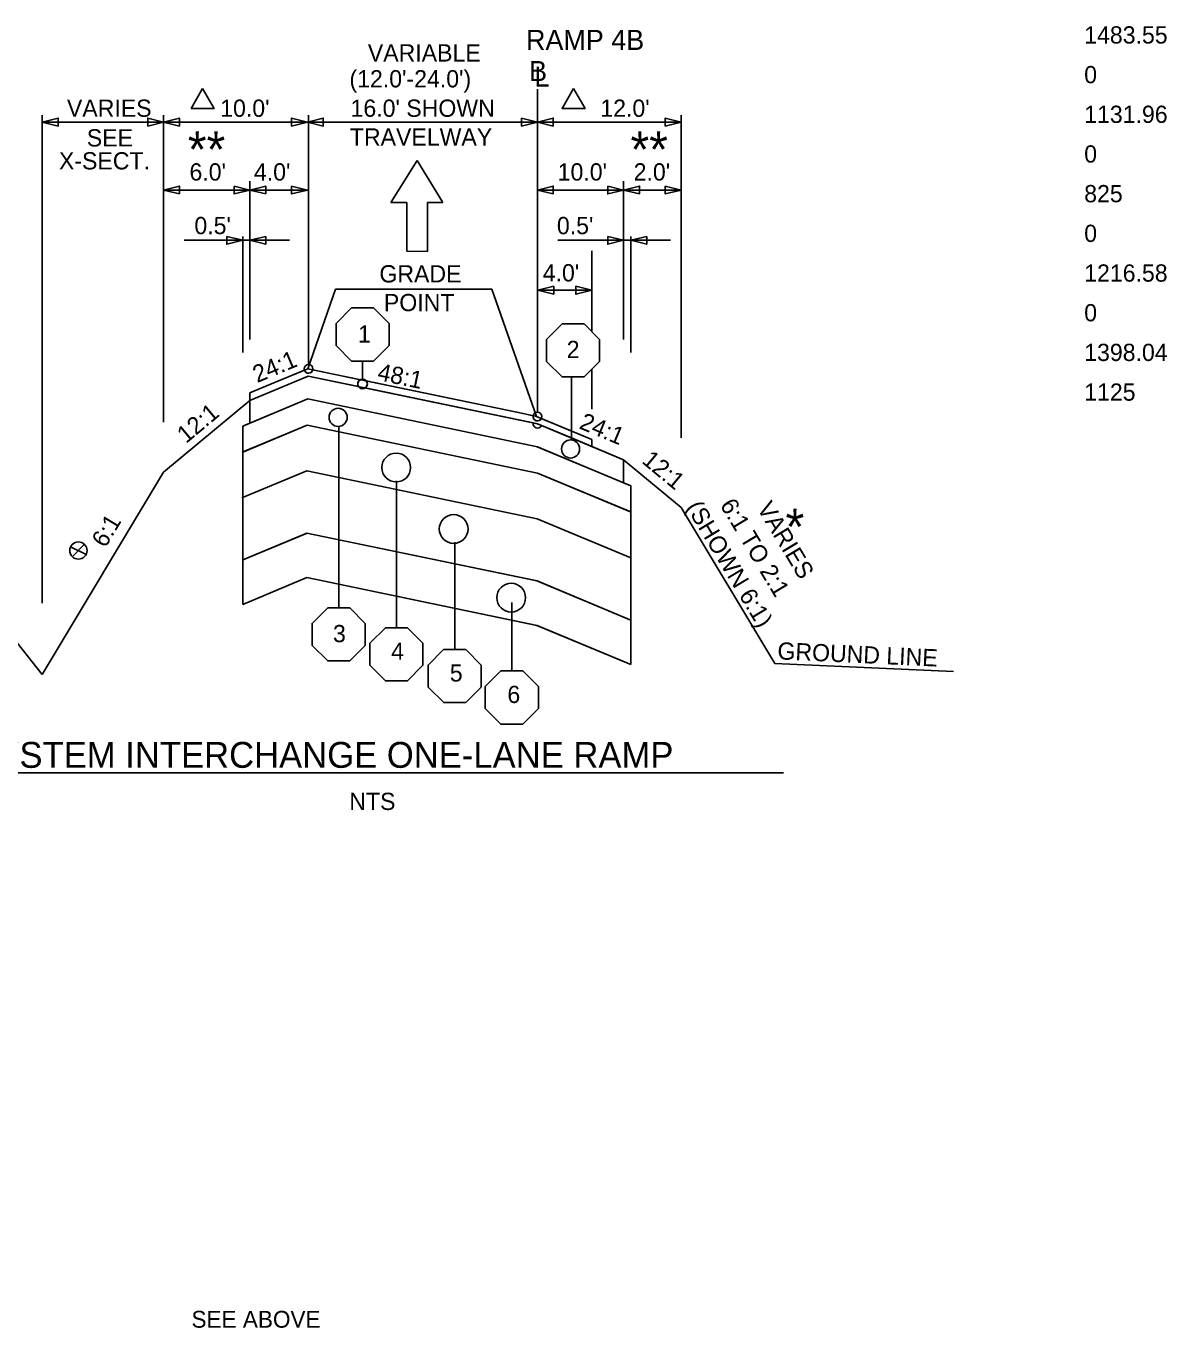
# Model space of a CAD drawing. Extents: x 4932 to 5887, y 4809 to 5473.
# Drawn here: x 5284.3 to 5363.6, y 5044.2 to 5134.7 of the extents above; entities that cross this region are included whole.
import ezdxf

# ---------------------------------------------------------------- set-up
doc = ezdxf.new("R2010")
doc.units = 0
for name, color, linetype in [('Level 2', 7, 'Continuous'), ('Level 20', 7, 'Continuous'), ('Level 25', 7, 'Continuous'), ('RD_QTY_Intermediate', 7, 'Continuous'), ('RD_QTY_Surf_Course', 7, 'Continuous'), ('RD_SHT_Typical', 7, 'Continuous'), ('RD_TX_TypSect', 7, 'Continuous'), ('RD_XS_ExGround', 7, 'Continuous'), ('typical2', 7, 'Continuous'), ('typical_on', 7, 'Continuous')]:
    doc.layers.add(name, color=color, linetype=linetype)

msp = doc.modelspace()

# ---------------------------------------------------------------- linework, layer by layer
at = {"layer": 'Level 2'}
for p, q in [((5299.854, 5107.109), (5299.854, 5107.109)), ((5299.854, 5107.054), (5299.854, 5107.054))]:
    msp.add_line(p, q, dxfattribs=at)
at = {"layer": 'Level 20'}
for p, q in [((5309.668, 5122.448), (5311.49, 5125.362)), ((5311.49, 5125.362), (5313.274, 5122.438)), ((5310.76, 5122.447), (5309.668, 5122.448)), ((5310.76, 5122.447), (5310.76, 5119.047)), ((5312.217, 5122.438), (5313.274, 5122.438)), ((5312.217, 5122.438), (5312.217, 5119.038)), ((5310.76, 5119.047), (5312.217, 5119.038))]:
    msp.add_line(p, q, dxfattribs=at)
at = {"layer": 'Level 25'}
for p, q in [((5303.875, 5110.876), (5305.818, 5116.411)), ((5305.818, 5116.411), (5316.674, 5116.411)), ((5316.674, 5116.411), (5319.78, 5107.562))]:
    msp.add_line(p, q, dxfattribs=at)
at = {"layer": 'RD_QTY_Intermediate'}
for p, q in [((5319.847, 5105.45), (5303.875, 5108.777)), ((5299.355, 5105.084), (5303.847, 5106.956)), ((5299.355, 5106.893), (5299.355, 5105.084)), ((5303.847, 5106.956), (5319.846, 5103.623)), ((5325.845, 5102.931), (5319.847, 5105.45)), ((5319.846, 5103.623), (5326.345, 5100.915)), ((5326.345, 5102.723), (5325.845, 5102.933)), ((5326.345, 5100.915), (5326.345, 5102.723))]:
    msp.add_line(p, q, dxfattribs=at)
for points in [[(5303.875, 5108.777), (5299.854, 5107.102), (5299.355, 5106.893)], [(5325.845, 5102.933), (5325.845, 5102.931)]]:
    msp.add_lwpolyline(points, dxfattribs=at)
at = {"layer": 'RD_QTY_Surf_Course'}
for p, q in [((5303.911, 5110.365), (5299.854, 5108.675)), ((5319.554, 5107.106), (5303.911, 5110.365)), ((5299.854, 5107.102), (5303.875, 5108.777)), ((5299.854, 5108.675), (5299.854, 5107.102)), ((5303.875, 5108.777), (5319.847, 5105.45)), ((5319.847, 5105.45), (5325.845, 5102.933)), ((5325.845, 5102.933), (5325.845, 5104.546))]:
    msp.add_line(p, q, dxfattribs=at)
msp.add_lwpolyline([(5325.845, 5104.546), (5322.209, 5106.061), (5320.124, 5106.93)], dxfattribs=at)
msp.add_circle((5322.152, 5105.298), 0.63, dxfattribs=at)
msp.add_arc((5319.847, 5107.045), 0.3, 168.23191, 337.38014, dxfattribs=at)
at = {"layer": 'RD_SHT_Typical'}
for p, q in [((5301.796, 5110.01), (5303.875, 5110.876)), ((5303.652, 5110.783), (5301.796, 5110.01)), ((5307.538, 5110.113), (5304.234, 5110.801)), ((5299.854, 5108.675), (5303.911, 5110.365)), ((5299.854, 5108.675), (5303.911, 5110.365)), ((5299.854, 5109.201), (5301.796, 5110.01)), ((5301.796, 5110.01), (5299.854, 5109.201)), ((5303.911, 5110.365), (5307.417, 5109.634)), ((5299.854, 5109.201), (5299.854, 5107.102)), ((5299.854, 5109.201), (5299.854, 5108.675)), ((5307.871, 5109.54), (5319.554, 5107.106)), ((5299.854, 5108.675), (5293.857, 5103.677)), ((5299.355, 5106.893), (5303.875, 5108.777)), ((5319.554, 5107.106), (5319.847, 5107.045)), ((5323.624, 5105.961), (5319.78, 5107.562)), ((5325.845, 5104.546), (5319.847, 5107.045)), ((5319.847, 5107.045), (5320.124, 5106.93)), ((5323.624, 5105.961), (5320.117, 5107.422)), ((5299.327, 5105.072), (5303.847, 5106.956)), ((5299.355, 5106.893), (5299.355, 5094.489)), ((5326.345, 5102.723), (5319.823, 5105.44)), ((5323.624, 5105.961), (5323.624, 5105.471)), ((5323.624, 5105.471), (5323.624, 5105.961)), ((5325.845, 5104.546), (5325.845, 5102.931)), ((5325.845, 5104.546), (5329.843, 5101.214)), ((5293.857, 5103.677), (5285.421, 5089.617)), ((5299.304, 5101.896), (5303.825, 5103.78)), ((5326.367, 5100.906), (5319.846, 5103.623)), ((5326.345, 5102.723), (5326.345, 5090.302)), ((5329.843, 5101.214), (5336.346, 5090.376)), ((5326.345, 5097.73), (5319.823, 5100.447)), ((5299.311, 5097.565), (5303.831, 5099.449)), ((5278.835, 5097.851), (5285.421, 5089.617)), ((5299.355, 5094.489), (5303.825, 5096.352)), ((5326.345, 5093.4), (5319.805, 5096.125)), ((5326.345, 5090.302), (5319.805, 5093.026))]:
    msp.add_line(p, q, dxfattribs=at)
for points in [[(5303.875, 5110.876), (5318.85, 5107.756), (5319.78, 5107.562)], [(5303.911, 5110.365), (5319.847, 5107.045)], [(5319.552, 5107.61), (5318.85, 5107.756), (5307.951, 5110.027)], [(5303.875, 5108.777), (5319.847, 5105.45)], [(5303.847, 5106.956), (5319.846, 5103.623)], [(5320.124, 5106.93), (5322.209, 5106.061), (5323.624, 5105.471)], [(5303.825, 5103.78), (5319.823, 5100.447)], [(5303.825, 5099.45), (5319.823, 5096.117)], [(5303.825, 5096.352), (5319.823, 5093.019)]]:
    msp.add_lwpolyline(points, dxfattribs=at)
for centre, radius, start, end in [((5303.941, 5110.862), 0.3, 195.36042, 348.23191), ((5307.693, 5109.819), 0.332, 117.69811, 213.83802), ((5307.693, 5109.819), 0.332, 302.6258, 38.76571), ((5319.846, 5107.549), 0.3, 168.23191, 334.96624)]:
    msp.add_arc(centre, radius, start, end, dxfattribs=at)
at = {"layer": 'RD_TX_TypSect'}
for p, q in [((5319.846, 5130.313), (5319.846, 5107.849)), ((5285.421, 5094.569), (5285.421, 5128.519)), ((5285.421, 5128.034), (5293.857, 5128.034)), ((5293.857, 5107.151), (5293.857, 5128.519)), ((5293.857, 5128.034), (5303.853, 5128.034)), ((5303.853, 5128.034), (5319.847, 5128.034)), ((5303.941, 5128.519), (5303.941, 5111.162)), ((5319.847, 5128.034), (5329.843, 5128.034)), ((5329.843, 5106.068), (5329.843, 5128.519)), ((5293.857, 5123.305), (5299.854, 5123.305)), ((5299.854, 5112.915), (5299.854, 5123.923)), ((5299.854, 5123.305), (5303.853, 5123.305)), ((5319.847, 5123.305), (5325.845, 5123.305)), ((5325.845, 5112.915), (5325.845, 5123.923)), ((5325.845, 5123.305), (5329.843, 5123.305)), ((5295.277, 5119.809), (5299.355, 5119.809)), ((5299.355, 5112.014), (5299.355, 5120.084)), ((5302.62, 5119.809), (5299.355, 5119.809)), ((5321.257, 5119.809), (5325.845, 5119.809)), ((5329.11, 5119.809), (5325.845, 5119.809)), ((5326.345, 5112.014), (5326.345, 5120.084)), ((5323.624, 5113.466), (5323.624, 5119.088)), ((5319.877, 5116.333), (5323.624, 5116.333)), ((5307.693, 5111.408), (5307.693, 5110.151)), ((5323.624, 5108.075), (5323.624, 5110.833)), ((5322.209, 5105.914), (5322.209, 5110.303)), ((5306.03, 5094.246), (5306.03, 5106.889)), ((5310.046, 5092.862), (5310.046, 5103.071)), ((5303.825, 5099.45), (5299.355, 5097.583)), ((5287.391, 5098.5), (5288.463, 5097.953)), ((5287.514, 5097.807), (5288.34, 5098.651)), ((5314.095, 5091.35), (5314.095, 5098.823)), ((5299.355, 5097.583), (5299.355, 5094.489)), ((5299.355, 5094.489), (5303.825, 5096.352)), ((5303.825, 5096.352), (5319.805, 5093.023)), ((5326.345, 5093.4), (5319.823, 5096.117)), ((5318.071, 5089.857), (5318.071, 5094.623)), ((5326.345, 5090.302), (5326.345, 5093.4)), ((5278.6, 5082.767), (5336.968, 5082.767))]:
    msp.add_line(p, q, dxfattribs=at)
for points in [[(5296.573, 5130.369), (5295.774, 5128.984), (5297.372, 5128.984)], [(5322.365, 5130.369), (5321.566, 5128.984), (5323.164, 5128.984)], [(5286.524, 5127.759), (5286.524, 5128.309), (5285.421, 5128.034)], [(5292.754, 5127.759), (5292.754, 5128.309), (5293.857, 5128.034)], [(5294.959, 5127.759), (5294.959, 5128.309), (5293.857, 5128.034)], [(5302.75, 5127.759), (5302.75, 5128.309), (5303.853, 5128.034)], [(5304.955, 5127.759), (5304.955, 5128.309), (5303.853, 5128.034)], [(5318.745, 5128.309), (5318.745, 5127.759), (5319.847, 5128.034)], [(5320.95, 5127.759), (5320.95, 5128.309), (5319.847, 5128.034)], [(5328.741, 5127.759), (5328.741, 5128.309), (5329.843, 5128.034)], [(5294.959, 5123.03), (5294.959, 5123.58), (5293.857, 5123.305)], [(5298.752, 5123.58), (5298.752, 5123.03), (5299.854, 5123.305)], [(5300.957, 5123.03), (5300.957, 5123.58), (5299.854, 5123.305)], [(5302.75, 5123.58), (5302.75, 5123.03), (5303.853, 5123.305)], [(5320.95, 5123.03), (5320.95, 5123.58), (5319.847, 5123.305)], [(5324.742, 5123.58), (5324.742, 5123.03), (5325.845, 5123.305)], [(5326.947, 5123.03), (5326.947, 5123.58), (5325.845, 5123.305)], [(5328.741, 5123.58), (5328.741, 5123.03), (5329.843, 5123.305)], [(5298.252, 5120.084), (5298.252, 5119.534), (5299.355, 5119.809)], [(5300.957, 5120.084), (5300.957, 5119.534), (5299.854, 5119.809)], [(5324.742, 5120.084), (5324.742, 5119.534), (5325.845, 5119.809)], [(5327.447, 5120.084), (5327.447, 5119.534), (5326.345, 5119.809)], [(5320.98, 5116.058), (5320.98, 5116.608), (5319.877, 5116.333)], [(5322.521, 5116.608), (5322.521, 5116.058), (5323.624, 5116.333)]]:
    msp.add_lwpolyline(points, close=True, dxfattribs=at)
for points in [[(5319.823, 5096.117), (5319.805, 5096.121), (5303.825, 5099.45)], [(5319.805, 5093.023), (5319.805, 5093.026)], [(5319.805, 5093.026), (5319.823, 5093.019), (5326.345, 5090.302)]]:
    msp.add_lwpolyline(points, dxfattribs=at)
for centre, radius in [((5303.941, 5110.862), 0.3), ((5307.693, 5109.819), 0.332), ((5305.993, 5107.494), 0.63), ((5319.846, 5107.549), 0.3), ((5322.152, 5105.298), 0.63), ((5310.028, 5104.005), 1), ((5314.026, 5099.731), 1), ((5287.933, 5098.232), 0.6), ((5318.028, 5094.952), 1), ((5318.028, 5094.952), 1)]:
    msp.add_circle(centre, radius, dxfattribs=at)
at = {"layer": 'RD_XS_ExGround'}
msp.add_line((5336.346, 5090.376), (5348.785, 5089.809), dxfattribs=at)
at = {"layer": 'typical_on'}
for points in [[(5309.54, 5114.019), (5309.54, 5112.489), (5308.458, 5111.408), (5306.929, 5111.408), (5305.847, 5112.489), (5305.847, 5114.019), (5306.928, 5115.101), (5308.458, 5115.101)], [(5324.176, 5112.914), (5324.176, 5111.385), (5323.094, 5110.303), (5321.565, 5110.303), (5320.483, 5111.385), (5320.483, 5112.914), (5321.564, 5113.996), (5323.094, 5113.996)], [(5307.876, 5093.165), (5307.876, 5091.635), (5306.795, 5090.554), (5305.265, 5090.553), (5304.184, 5091.635), (5304.184, 5093.165), (5305.265, 5094.246), (5306.795, 5094.246)], [(5311.892, 5091.781), (5311.892, 5090.251), (5310.811, 5089.169), (5309.281, 5089.169), (5308.2, 5090.251), (5308.2, 5091.781), (5309.281, 5092.862), (5310.811, 5092.862)], [(5315.942, 5090.268), (5315.942, 5088.739), (5314.86, 5087.657), (5313.331, 5087.657), (5312.249, 5088.739), (5312.249, 5090.268), (5313.33, 5091.35), (5314.86, 5091.35)], [(5319.918, 5088.776), (5319.918, 5087.246), (5318.836, 5086.165), (5317.307, 5086.164), (5316.225, 5087.246), (5316.225, 5088.776), (5317.307, 5089.857), (5318.836, 5089.857)]]:
    msp.add_lwpolyline(points, close=True, dxfattribs=at)

# ---------------------------------------------------------------- texts
at = {"layer": 'RD_TX_TypSect'}
for s, height, p in [('RAMP 4B', 1.4, (5319.054, 5133.046)), ('1483.55', 1.2, (5357.867, 5133.494)), ('B', 1.4, (5319.269, 5130.88)), ('L', 1.4, (5319.641, 5130.494)), ('0', 1.2, (5357.867, 5130.734)), ('VARIES', 1.2, (5287.136, 5128.398)), ("10.0'", 1.2, (5297.793, 5128.398)), ("16.0' SHOWN", 1.2, (5306.857, 5128.398)), ("12.0'", 1.2, (5324.223, 5128.398)), ('1131.96', 1.2, (5357.867, 5127.974)), ('SEE', 1.2, (5288.517, 5126.335)), ('**', 2.5, (5295.545, 5124.879)), ('TRAVELWAY', 1.2, (5306.807, 5126.398)), ('**', 2.5, (5326.319, 5124.879)), ('0', 1.2, (5357.867, 5125.214)), ('X-SECT.', 1.2, (5286.58, 5124.738)), ("6.0'", 1.2, (5295.656, 5123.966)), ("4.0'", 1.2, (5300.138, 5123.966)), ("10.0'", 1.2, (5321.258, 5123.966)), ("2.0'", 1.2, (5326.542, 5123.966)), ('825', 1.2, (5357.867, 5122.454)), ("0.5'", 1.2, (5295.999, 5120.235)), ("0.5'", 1.2, (5321.203, 5120.235)), ('0', 1.2, (5357.867, 5119.694)), ('GRADE', 1.2, (5308.863, 5116.879)), ("4.0'", 1.2, (5320.218, 5116.948)), ('1216.58', 1.2, (5357.867, 5116.934)), ('POINT', 1.2, (5309.175, 5114.879)), ('0', 1.2, (5357.867, 5114.174)), ('1', 1.2, (5307.375, 5112.693)), ('2', 1.2, (5321.884, 5111.618)), ('1398.04', 1.2, (5357.867, 5111.414)), ('1125', 1.2, (5357.867, 5108.654)), ('*', 2.5, (5337.102, 5098.639)), ('3', 1.2, (5305.634, 5091.858)), ('4', 1.2, (5309.68, 5090.631)), ('5', 1.2, (5313.757, 5089.119)), ('6', 1.2, (5317.761, 5087.627)), ('SYSTEM INTERCHANGE ONE-LANE RAMP', 1.8, (5280.623, 5083.12)), ('NTS', 1.2, (5306.768, 5080.187))]:
    msp.add_text(s, height=height, dxfattribs=at).set_placement(p)
for s, rotation, p in [('VARIABLE', 0.00163, (5308.058, 5132.243)), ("(12.0'-24.0')", 0.00163, (5306.78, 5130.443)), ('24:1', 22.61905, (5300.366, 5109.877)), ('48:1', 348.23171, (5308.665, 5110.101)), ('12:1', 39.80557, (5295.419, 5105.638)), ('24:1', 337.38014, (5322.681, 5106.748)), ('12:1', 320.19386, (5327.041, 5104.377)), ('(SHOWN 6:1)', 300.96376, (5330.156, 5101.239)), ('6:1 TO 2:1', 300.96376, (5332.51, 5101.395)), ('VARIES', 300.96376, (5335.086, 5101.183)), ('6:1', 59.03624, (5289.809, 5098.365)), ('GROUND LINE', 357.39046, (5336.517, 5090.667))]:
    msp.add_text(s, height=1.2, rotation=rotation, dxfattribs=at).set_placement(p)
at = {"layer": 'typical2'}
msp.add_text('SEE ABOVE', height=1.1726, dxfattribs=at).set_placement((5295.794, 5044.179))

doc.saveas('drawing.dxf')
